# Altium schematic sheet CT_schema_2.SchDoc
size 293 x 156 mm
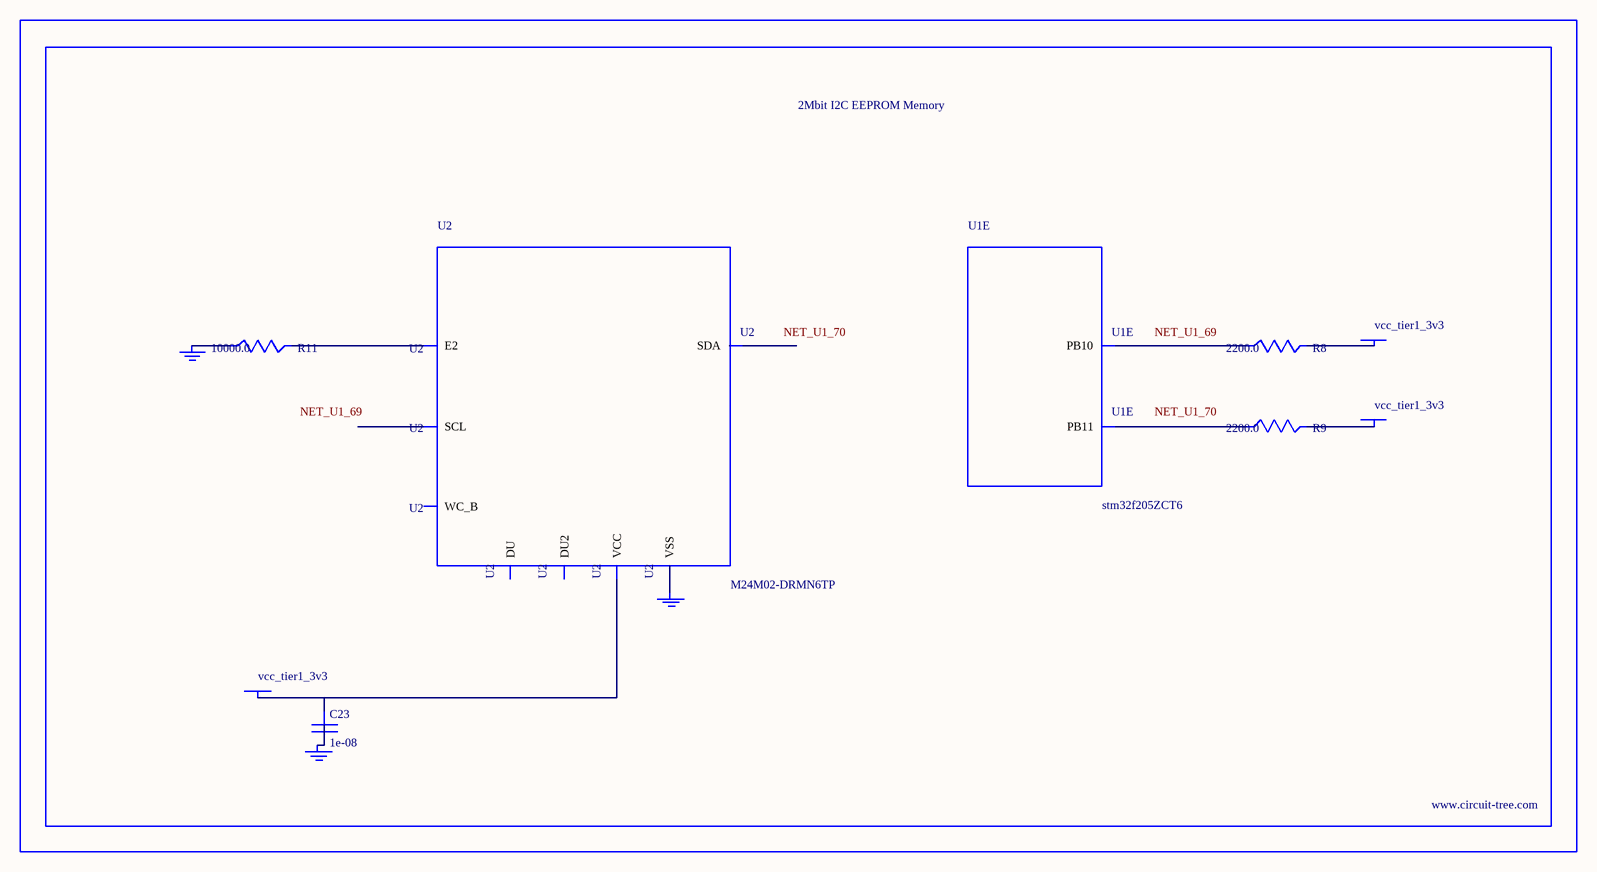
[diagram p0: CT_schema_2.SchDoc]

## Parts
BORDER1  (no value)
C23  1e-08  [C0402]
GND_INSTANCE_1_0  (no value)
GND_INSTANCE_1_1  (no value)
GND_INSTANCE_1_2  (no value)
POWER_INSTANCE_1_0  vcc_tier1_3v3
POWER_INSTANCE_1_1  vcc_tier1_3v3
POWER_INSTANCE_1_2  vcc_tier1_3v3
R8  2200.0  [R0603]
R9  2200.0  [R0603]
R11  10000.0  [R0603]
U1  stm32f205ZCT6  [LQFP144]  (part E of 12)
U2  M24M02-DRMN6TP  [SOIC-8]

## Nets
NetC23_1: C23.1 POWER_INSTANCE_1_0.0(PWR) U2.8(VCC)
NetC23_2: C23.2 GND_INSTANCE_1_1.0(GND)
NetGND_INSTANCE_1_0_0: GND_INSTANCE_1_0.0(GND) R11.1
NetGND_INSTANCE_1_2_0: GND_INSTANCE_1_2.0(GND) U2.4(VSS)
NetPOWER_INSTANCE_1_1_0: POWER_INSTANCE_1_1.0(PWR) R8.2
NetPOWER_INSTANCE_1_2_0: POWER_INSTANCE_1_2.0(PWR) R9.2
NetR8_1: R8.1 U1.69(PB10)
NetR9_1: R9.1 U1.70(PB11)
NetR11_2: R11.2 U2.3(E2)

Not connected (* = marked no-connect by the designer): U2 1(DU) 2(DU2) 5(SDA) 6(SCL) 7(WC_B)

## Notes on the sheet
- Labels drawn without touching a wire or pin: NET_U1_69, NET_U1_70

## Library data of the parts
BORDER1 = BORDER_PAGE1
C23 = C0402C103K3RAC
GND_INSTANCE_1_0-GND_INSTANCE_1_2 = GND
POWER_INSTANCE_1_0-POWER_INSTANCE_1_2 = PWR
R8 R9 = RC0603JR-072K2L
R11 = RC0603JR-0710KL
